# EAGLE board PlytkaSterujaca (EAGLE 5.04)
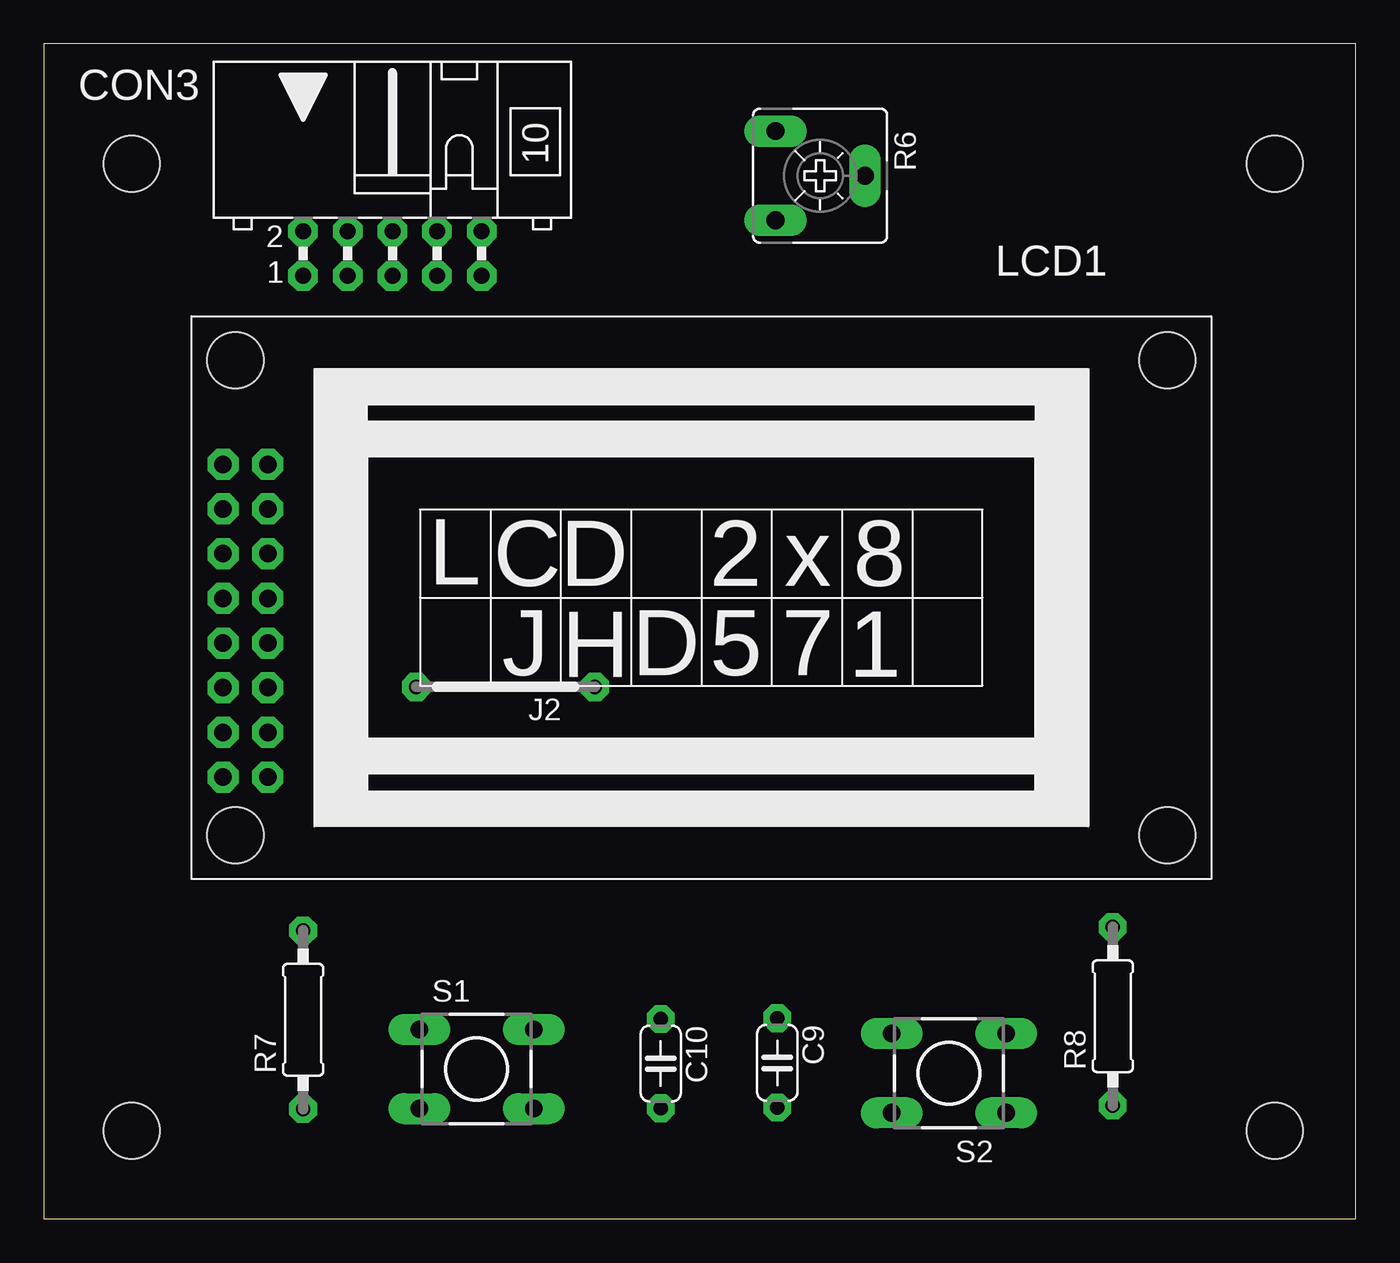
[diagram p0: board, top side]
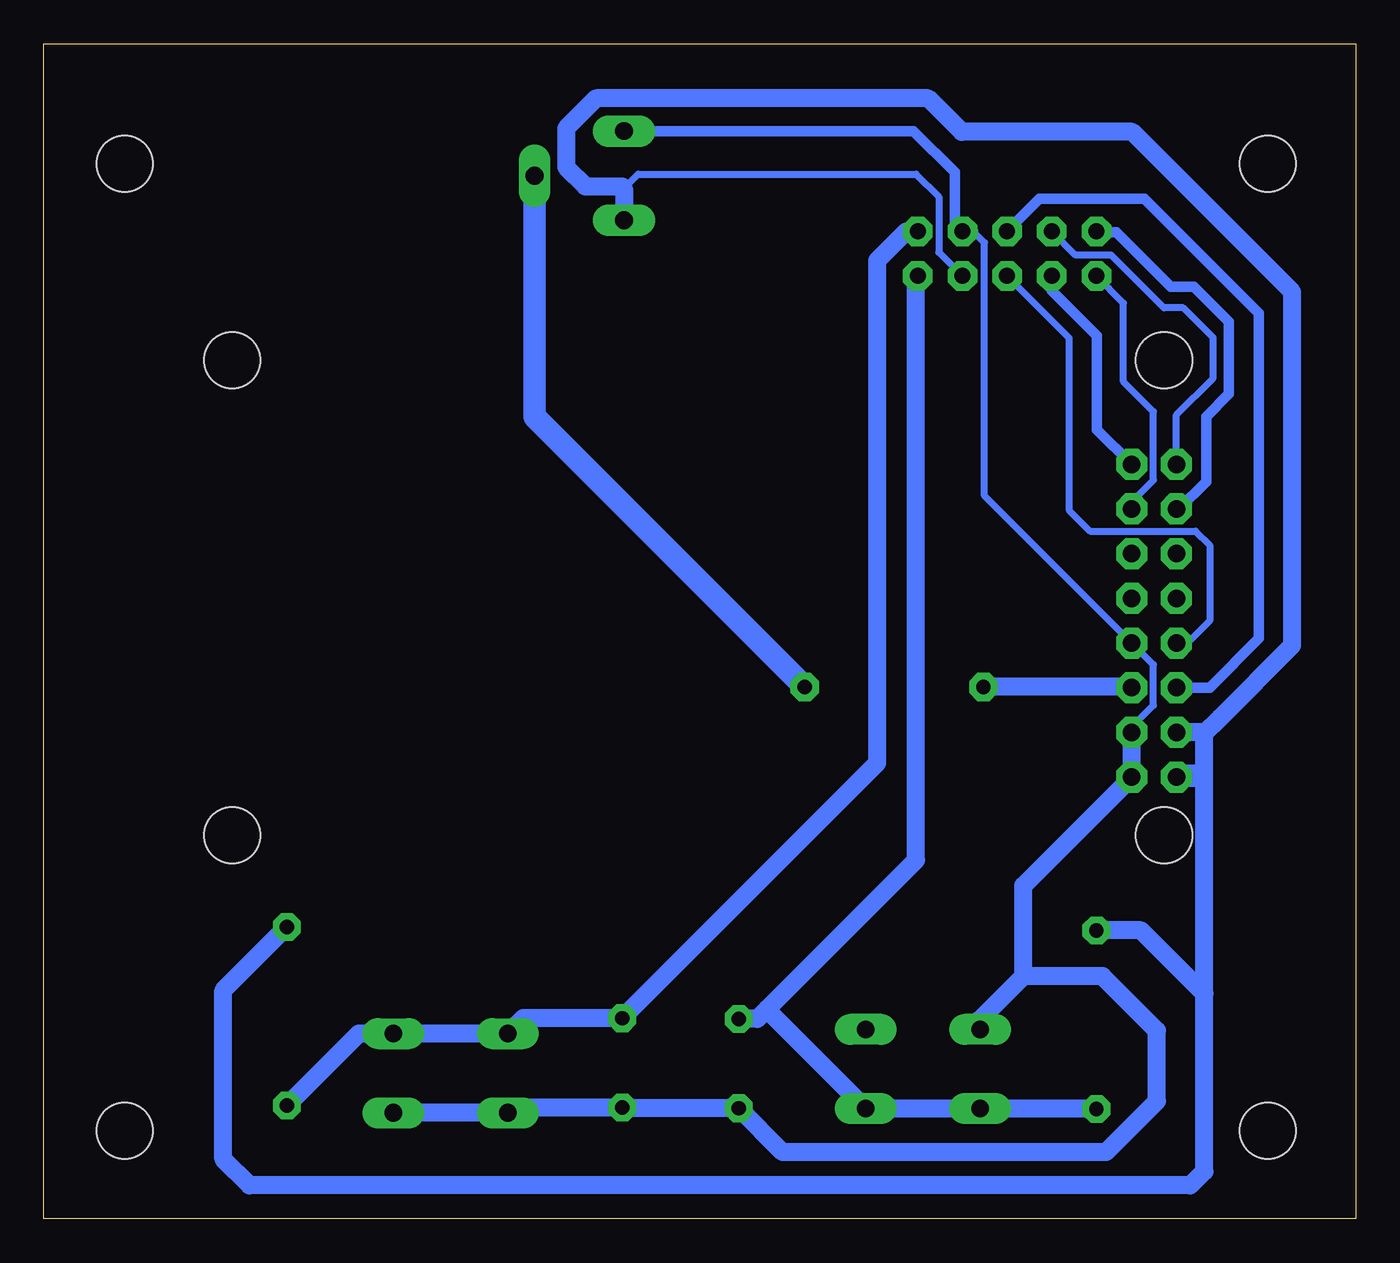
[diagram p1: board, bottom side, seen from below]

Size 74.6 x 66.8 mm. Coordinates in mm from the lower left corner, seen from the top.
Outline: 0,0 74.6,0 74.6,66.8 0,66.8 0,0
Copper layers (1*16): Top 0.035mm / dielectric 1.5mm / Bottom 0.035mm
Design rules "default *": minimum track width 10mil, minimum drill 24mil, track to track 8mil, track to pad 8mil, pad to pad 8mil, via to via 8mil, smd to smd 8mil, copper to edge 40mil, drill to drill 8mil, minimum pad ring 15mil, minimum via ring 8mil, stop-mask expansion 4mil, vias tented up to drill 0mil, thermal gap 10mil
Holes 3.2 mm at 5,60 70,60 70,5 5,5

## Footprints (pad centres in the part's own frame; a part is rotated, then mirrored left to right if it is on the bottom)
C050-024X044 = drill 0.813 octagon: 1 -2.54,0; 2 2.54,0
ML10L = drill 0.914 octagon: 1 -5.08,-1.27; 2 -5.08,1.27; 3 -2.54,-1.27; 4 -2.54,1.27; 5 0,-1.27; 6 0,1.27; 7 2.54,-1.27; 8 2.54,1.27; 9 5.08,-1.27; 10 5.08,1.27
10 = drill 0.813 pad 1.6 octagon: 1 -5.08,0; 2 5.08,0
LCDJHD571 = drill 1 octagon: DB0 4.34,15.96; DB1 1.8,15.96; DB2 4.34,18.5; DB3 1.8,18.5; DB4 4.34,21.04; DB5 1.8,21.04; DB6 4.34,23.58; DB7 1.8,23.58; E 1.8,13.42; LED+ 4.34,5.8; LED- 1.8,5.8; R/W 4.34,13.42; RS 1.8,10.88; V0 4.34,10.88; VDD 1.8,8.34; VSS 4.34,8.34 | hole 3.2: 2.5,2.5; 2.5,29.5; 55.5,29.5; 55.5,2.5
CA6V = drill 1.016 long: A -2.54,-2.54; E 2.54,-2.54; S 0,2.54
0207/10 = drill 0.813 octagon: 1 -5.08,0; 2 5.08,0
DTS-6 = drill 1 long: 1 -3.25,2.25; 2 3.25,2.25; 3 -3.25,-2.25; 4 3.25,-2.25

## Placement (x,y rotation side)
C9  100nF  [C050-024X044]  41.71,8.87 270 top
C10  100nF  [C050-024X044]  35.08,8.83 270 top
CON3  IDC10L  [ML10L]  19.82,54.88 0 top
J2  J10MM  [10]  26.25,30.24 180 top
LCD1  LCD-JHD721-2X8  [LCDJHD571]  8.39,19.32 0 top
R6  [CA6V]  44.15,59.31 270 top
R7  10k  [0207/10]  14.74,11.32 90 top
R8  10k  [0207/10]  60.79,11.52 90 top
S1  DTS-6  [DTS-6]  24.6,8.52 0 top
S2  DTS-6  [DTS-6]  51.47,8.28 180 top

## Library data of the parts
C9 C10 R7 R8 = resistor
CON3 = con-harting-ml
J2 = jumper
LCD1 = LCD2x8
R6 = pot
S1 S2 = switch-tact

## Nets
N$1: CON3.7 LCD1.VDD R6.E R7.2 R8.2
N$2: J2.2 LCD1.V0
N$29: CON3.5 LCD1.E
N$30: J2.1 R6.S
N$32: C9.2 C10.2 CON3.8 LCD1.LED+ LCD1.R/W LCD1.VSS R6.A S1.1 S2.1 S2.2
N$33: CON3.4 LCD1.DB7
N$34: CON3.6 LCD1.RS
N$35: CON3.3 LCD1.DB6
N$36: CON3.2 LCD1.DB5
N$37: CON3.1 LCD1.DB4
N$38: C10.1 CON3.9 R7.1 S1.3 S1.4
N$39: C9.1 CON3.10 R8.1 S2.3 S2.4

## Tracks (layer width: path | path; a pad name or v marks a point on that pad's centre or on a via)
N$1
  Bottom 0.406: CON3.7 23.7,54.95 23.7,58.1 25,59.4 40.8,59.4 41.61,58.59
  Bottom 0.61: 7.7,28.5 8.54,27.66 | 41.72,58.7 41.61,58.59
  Bottom 1.016: 41.61,58.59 R6.E | 8.54,27.66 LCD1.VDD | 41.72,58.7 43.8,58.7 44.9,59.8 44.9,62 43.2,63.7 24.3,63.7 22.4,61.8 12.7,61.8 3.6,52.7 3.6,32.6 7.7,28.5 8.6,27.6 8.6,12.8 | R8.2 64.4,12.99 64.4,3.4 62.9,1.9 9.4,1.9 8.6,2.7 8.6,12.8 | 8.6,12.8 12.2,16.4 R7.2
N$2
  Bottom 1.016: LCD1.V0 12.77,30.24 J2.2
N$29
  Bottom 0.406: CON3.5 16.3,50.09 16.3,40.3 15.1,39.1 9.1,39.1 8.3,38.3 8.3,34 9.56,32.74 LCD1.E
N$30
  Bottom 1.27: J2.1 46.69,45.6 R6.S
N$32
  Bottom 0.406: 12.73,27.97 11.5,29.2 11.5,31.51 LCD1.R/W 21.1,41.11 21.1,55.5 21.75,56.15
  Bottom 0.61: LCD1.VSS 12.73,27.97 | 21.75,56.15 CON3.8 22.8,56.59 22.8,59.5 25.15,61.85 R6.A | 41.67,6.29 C9.2 42.01,6.03
  Bottom 1.016: S2.1 S2.2 47.92,6.33 C9.2 | 41.67,6.29 C10.2 32.59,3.8 14.2,3.8 11.3,6.7 11.3,10.7 14.4,13.8 18.9,13.8 | 18.9,13.8 21.35,11.35 S1.1 | LCD1.VSS LCD1.LED+ 18.9,18.95 18.9,13.8
N$33
  Bottom 0.406: LCD1.DB7 10.19,45.71 8.1,47.8 8.1,50.1 9.8,51.8 10.9,51.8 13.9,54.8 15.93,54.8 CON3.4
N$34
  Bottom 0.61: CON3.6 17.97,58 12,58 5.5,51.5 5.5,33 8.3,30.2 LCD1.RS
N$35
  Bottom 0.61: CON3.3 17.28,52.78 14.7,50.2 14.7,44.87 LCD1.DB6
N$36
  Bottom 0.61: LCD1.DB5 10.04,40.36 8.5,41.9 8.5,45.6 7.2,46.9 7.2,51 9.2,53 10.5,53 13.6,56.1 14.69,56.1 CON3.2
N$37
  Bottom 0.406: 12.73,40.77 11.5,42 11.5,45.9 13.2,47.6 13.2,52.07 CON3.1
  Bottom 0.61: LCD1.DB4 12.73,40.77
N$38
  Bottom 1.016: CON3.9 25,53.51 25,20.4 33.45,11.95 | 33.45,11.95 34.03,11.37 C10.1 | R7.1 14.77,6.27 S1.3 S1.4 33.45,11.87 33.45,11.95
N$39
  Bottom 1.016: R8.1 56.7,10.53 S2.3 S2.4 47.34,11.41 C9.1 27.2,25.92 27.2,54.5 25.55,56.15 CON3.10
S$1
  Bottom 1.27: 10.3,25.2 8.8,25.2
